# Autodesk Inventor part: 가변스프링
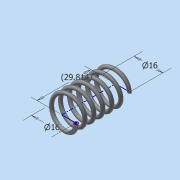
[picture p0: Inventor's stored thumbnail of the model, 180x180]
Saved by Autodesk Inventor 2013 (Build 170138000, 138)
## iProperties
Created: 2018-07
Part Number: 가변스프링
Material: 일반
Document SubType Name: Modeling
Designer: dgall
Density: 1 g/cm^3
Mass: -0.014375 g
Surface Area: 18.9209 cm^2
Volume: -0.014375 cm^3
Author: dgall
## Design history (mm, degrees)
sketch "스케치1"
  geometry: L1 (0, 0)-(0, 29.814); L2 (0, 29.814)-(8, 29.814); L3 (0, 0)-(8, 0); C1 r 1 at (8, 0)
  constraints: 6 end point, 1 centre point, 1 coincident, 1 parallel, 1 perpendicular, 1 vertical
  dimensions: "d0" = 29.81359 distance of L1.start L1.end (derived); "d1" = 16 diameter of L2.end L1; "d2" = 16 diameter of L3.end L1
feature "코일1" pitch "d3" = 10; turns "d5" = 6; dims "d4" = 29.81359 (= d0), "d6" = 0, angle "d7" = 90 deg, angle "d8" = 90 deg, "d9" = 0, "d10" = 0
node "작업 평면1"
feature "분할1"
feature "분할2"
node "솔리드1"
